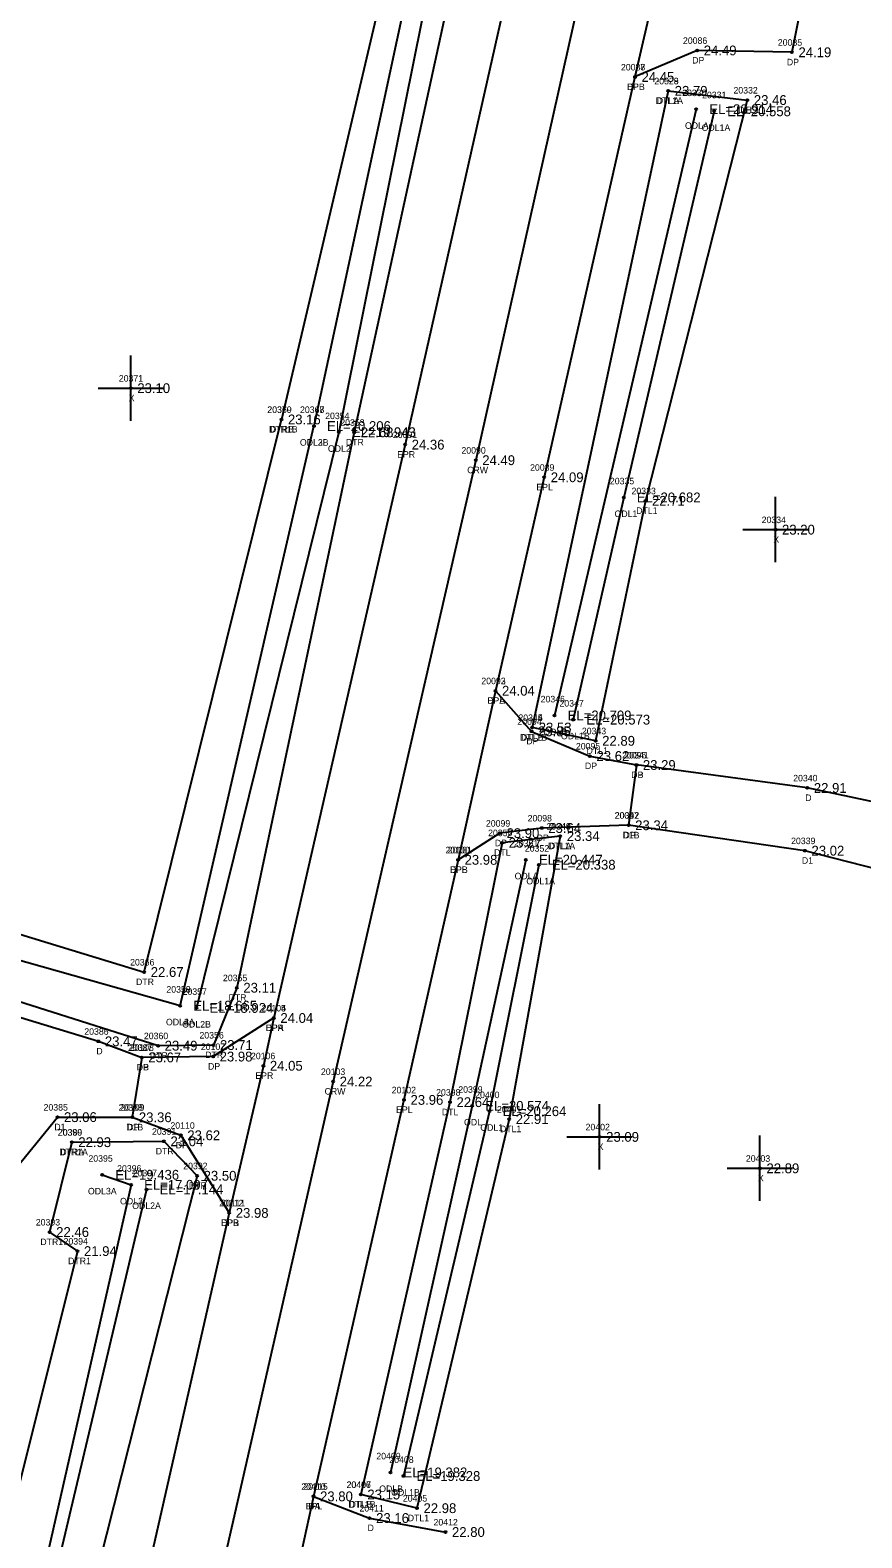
# Model space of a CAD drawing. Extents: x 2655177 to 2656219, y 761780 to 764748.
# Drawn here: x 2655809.5 to 2655936.8, y 763790 to 764020.7 of the extents above; entities that cross this region are included whole.
import ezdxf

# ---------------------------------------------------------------- set-up
doc = ezdxf.new("R2010")
doc.units = 0
for name, color, linetype in [('RD_DTM_BkLn1', 7, 'Continuous'), ('RD_EX_Driveway', 7, 'Continuous'), ('RD_EX_Driveway_txCode', 7, 'Continuous'), ('RD_EX_H2O', 7, 'Continuous'), ('RD_EX_H2O_txCode', 7, 'Continuous'), ('RD_EX_Misc', 7, 'Continuous'), ('RD_EX_Misc_txCode', 7, 'Continuous'), ('RD_EX_Road', 7, 'Continuous'), ('RD_EX_Road_txCode', 7, 'Continuous'), ('RD_EX_TX_Driveway_ELEV', 7, 'Continuous'), ('RD_EX_TX_H2O_ELEV', 7, 'Continuous'), ('RD_EX_TX_Misc_ELEV', 7, 'Continuous'), ('RD_EX_TX_Road_ELEV', 7, 'Continuous'), ('RD_HC_Survey_ELEV', 7, 'Continuous'), ('RD_HC_Survey_txCode', 7, 'Continuous'), ('RD_SMD_Locator', 7, 'Continuous')]:
    doc.layers.add(name, color=color, linetype=linetype)

msp = doc.modelspace()

# ---------------------------------------------------------------- linework, layer by layer
at = {"layer": 'RD_DTM_BkLn1'}
msp.add_lwpolyline([(2656052.36, 764720.46), (2656029.22, 764619.66), (2656007.41, 764523.97), (2655985.61, 764427.64), (2655963.53, 764330.64), (2655941.2, 764233.56), (2655920.06, 764141.06), (2655898.52, 764047.86), (2655877.71, 763954.88), (2655855.89, 763859.81), (2655834.07, 763763.97), (2655811.81, 763666.79), (2655790.48, 763573.22), (2655769.27, 763483.63), (2655747.64, 763389.32), (2655725.4, 763293.96), (2655721.51, 763275.9)], dxfattribs=at)
at = {"layer": 'RD_EX_Driveway'}
for points in [[(2655908.15, 764039.87), (2655916.78, 764031.64), (2655928.16, 764027.89), (2655926.1, 764017.29), (2655911.6, 764017.57), (2655902.08, 764013.51)], [(2655880.73, 763919.6), (2655886.23, 763913.39), (2655895.19, 763909.61), (2655902.29, 763908.24), (2655901.11, 763899.02), (2655887.81, 763898.6), (2655881.42, 763897.81), (2655875, 763893.73)], [(2655968.03, 763896.35), (2655928.45, 763904.73), (2655902.29, 763908.24)], [(2655965.98, 763885.43), (2655928.09, 763895.13), (2655901.11, 763899.02)], [(2655759.7, 763884.33), (2655819.96, 763865.96), (2655826.61, 763863.5)], [(2655846.82, 763869.53), (2655837.52, 763863.63), (2655826.61, 763863.5), (2655825.16, 763854.34), (2655832.58, 763851.58), (2655839.99, 763839.71)], [(2655797.92, 763834.98), (2655813.7, 763854.36), (2655825.16, 763854.34)], [(2655852.89, 763796.34), (2655861.47, 763793.02), (2655873.08, 763790.88)]]:
    msp.add_lwpolyline(points, dxfattribs=at)
at = {"layer": 'RD_EX_H2O'}
for p, q in [((2655907.16, 764011.39), (2655886.35, 763913.97)), ((2655911.46, 764008.58), (2655889.78, 763915.82)), ((2655832.49, 763871.41), (2655852.96, 763960.1)), ((2655832.49, 763871.41), (2655760.74, 763891.62))]:
    msp.add_line(p, q, dxfattribs=at)
for points in [[(2655985.99, 764532.58), (2655990.84, 764527.53), (2655967.74, 764432.27), (2655946, 764335.4), (2655922.66, 764238.07), (2655902.06, 764145.42), (2655879.59, 764053.25), (2655859.1, 763959.14), (2655841.15, 763874.16), (2655837.57, 763865.39), (2655829.11, 763865.29), (2655761.29, 763886.78)], [(2655985.99, 764532.58), (2655980.45, 764530.42), (2655978.53, 764524.06), (2655957.73, 764434.81), (2655933.82, 764338.64), (2655911.79, 764241.24), (2655890.59, 764146.77), (2655869.91, 764054.39), (2655847.97, 763961.11)], [(2655986.13, 764527.03), (2655964.81, 764432.99), (2655941.76, 764337.09), (2655920.19, 764238.99), (2655899.24, 764145.84), (2655875.75, 764053.31), (2655856.78, 763959.16), (2655834.97, 763871.07)], [(2655983.66, 764527.79), (2655962.07, 764433.73), (2655939.64, 764337.32), (2655916.77, 764240.59), (2655893.69, 764145.91), (2655873.09, 764053.84), (2655852.96, 763960.1)], [(2655907.16, 764011.39), (2655919.27, 764009.98), (2655903.67, 763948.66), (2655896.06, 763911.94), (2655886.35, 763913.97)], [(2655914.18, 764008.26), (2655900.36, 763949.18), (2655892.64, 763915.18)], [(2655761.3, 763896.61), (2655826.98, 763876.56), (2655847.97, 763961.11)], [(2655890.65, 763897.36), (2655881.76, 763896.35), (2655873.77, 763856.65), (2655860.12, 763796.62)], [(2655890.65, 763897.36), (2655882.83, 763854.06), (2655868.72, 763794.53), (2655860.12, 763796.62)], [(2655885.39, 763893.75), (2655877.16, 763856.09), (2655864.66, 763800)], [(2655887.35, 763892.98), (2655879.82, 763855.27), (2655866.65, 763799.45)], [(2655815.89, 763850.53), (2655830, 763850.66), (2655835.07, 763845.39), (2655815.37, 763767.48), (2655802.69, 763714.59), (2655797.51, 763669.56), (2655775.58, 763577.47), (2655772.9, 763561.56), (2655766.24, 763554.89), (2655760.22, 763554.42), (2655752.64, 763557.5), (2655751.61, 763561.47)], [(2655815.89, 763850.53), (2655812.51, 763836.78), (2655816.76, 763833.86), (2655801.46, 763772.79), (2655777.62, 763675.45), (2655757.45, 763580.99)], [(2655820.56, 763845.54), (2655824.97, 763844.01), (2655808.26, 763770.16), (2655784.18, 763674.18), (2655763.92, 763579.41), (2655759.35, 763565.01)], [(2655827.33, 763843.31), (2655809.9, 763769.59), (2655786.05, 763673.96), (2655766.11, 763579.1), (2655763.77, 763564.68)]]:
    msp.add_lwpolyline(points, dxfattribs=at)
at = {"layer": 'RD_EX_Misc'}
for p, q in [((2655824.92, 763960.9), (2655824.92, 763970.9)), ((2655819.92, 763965.9), (2655829.92, 763965.9)), ((2655923.58, 763939.25), (2655923.58, 763949.25)), ((2655918.58, 763944.25), (2655928.58, 763944.25)), ((2655896.67, 763846.34), (2655896.67, 763856.34)), ((2655891.67, 763851.34), (2655901.67, 763851.34)), ((2655921.2, 763841.53), (2655921.2, 763851.53)), ((2655916.2, 763846.53), (2655926.2, 763846.53))]:
    msp.add_line(p, q, dxfattribs=at)
at = {"layer": 'RD_EX_Road'}
for points in [[(2656041.72, 764723.31), (2656018.5, 764622.03), (2656002.75, 764552.49), (2655997.43, 764530.02), (2655974.74, 764429.64), (2655952.97, 764333.57), (2655930.52, 764235.7), (2655909.18, 764142.93), (2655887.93, 764050.57), (2655866.91, 763957.26), (2655846.82, 763869.53), (2655845.21, 763862.22), (2655839.99, 763839.71), (2655823.38, 763766.66), (2655801.33, 763669.93), (2655780.03, 763576.53), (2655774.26, 763551.85), (2655771.37, 763539.86), (2655759.09, 763486.9), (2655736.94, 763391.72), (2655715.19, 763296.77), (2655711.35, 763278.45)], [(2655930.84, 764138.62), (2655926.81, 764121.01), (2655909.26, 764045.26), (2655908.15, 764039.87), (2655902.08, 764013.51), (2655888.19, 763952.26), (2655880.73, 763919.6), (2655875, 763893.73), (2655866.73, 763857), (2655852.89, 763796.34), (2655850.73, 763786.52), (2655844.88, 763760.97), (2655822.62, 763664.7), (2655801.12, 763571.82), (2655780.32, 763481.64), (2655758.16, 763386.38), (2655736.73, 763291.27), (2655733.33, 763273.46)]]:
    msp.add_lwpolyline(points, dxfattribs=at)
at = {"layer": 'RD_SMD_Locator'}
for centre in [(2655911.6, 764017.57), (2655926.1, 764017.29), (2655902.08, 764013.51), (2655902.08, 764013.51), (2655907.16, 764011.39), (2655907.16, 764011.39), (2655919.27, 764009.98), (2655911.46, 764008.58), (2655914.18, 764008.26), (2655824.92, 763965.9), (2655847.97, 763961.11), (2655847.97, 763961.11), (2655852.96, 763960.1), (2655852.96, 763960.1), (2655856.78, 763959.16), (2655859.1, 763959.14), (2655866.91, 763957.26), (2655877.71, 763954.88), (2655888.19, 763952.26), (2655900.36, 763949.18), (2655903.67, 763948.66), (2655923.58, 763944.25), (2655880.73, 763919.6), (2655880.73, 763919.6), (2655889.78, 763915.82), (2655892.64, 763915.18), (2655886.23, 763913.39), (2655886.35, 763913.97), (2655886.35, 763913.97), (2655896.06, 763911.94), (2655895.19, 763909.61), (2655902.29, 763908.24), (2655902.29, 763908.24), (2655928.45, 763904.73), (2655901.11, 763899.02), (2655901.11, 763899.02), (2655881.42, 763897.81), (2655887.81, 763898.6), (2655890.65, 763897.36), (2655890.65, 763897.36), (2655881.76, 763896.35), (2655928.09, 763895.13), (2655875, 763893.73), (2655875, 763893.73), (2655885.39, 763893.75), (2655887.35, 763892.98), (2655826.98, 763876.56), (2655841.15, 763874.16), (2655832.49, 763871.41), (2655832.49, 763871.41), (2655834.97, 763871.07), (2655846.82, 763869.53), (2655846.82, 763869.53), (2655819.96, 763865.96), (2655829.11, 763865.29), (2655837.57, 763865.39), (2655826.61, 763863.5), (2655826.61, 763863.5), (2655837.52, 763863.63), (2655845.21, 763862.22), (2655855.89, 763859.81), (2655866.73, 763857), (2655873.77, 763856.65), (2655877.16, 763856.09), (2655879.82, 763855.27), (2655813.7, 763854.36), (2655825.16, 763854.34), (2655825.16, 763854.34), (2655882.83, 763854.06), (2655815.89, 763850.53), (2655815.89, 763850.53), (2655830, 763850.66), (2655832.58, 763851.58), (2655896.67, 763851.34), (2655921.2, 763846.53), (2655820.56, 763845.54), (2655824.97, 763844.01), (2655835.07, 763845.39), (2655827.33, 763843.31), (2655839.99, 763839.71), (2655839.99, 763839.71), (2655812.51, 763836.78), (2655816.76, 763833.86), (2655864.66, 763800), (2655866.65, 763799.45), (2655852.89, 763796.34), (2655852.89, 763796.34), (2655860.12, 763796.62), (2655860.12, 763796.62), (2655861.47, 763793.02), (2655868.72, 763794.53), (2655873.08, 763790.88)]:
    msp.add_circle(centre, 0.15, dxfattribs=at)

# ---------------------------------------------------------------- texts
at = {"layer": 'RD_EX_Driveway_txCode'}
for s, p in [('20086', (2655909.42, 764018.57)), ('20085', (2655923.94, 764018.29)), ('20087', (2655899.93, 764014.51)), ('DP', (2655910.83, 764015.57)), ('DP', (2655925.32, 764015.29)), ('DPB', (2655900.83, 764011.51)), ('20093', (2655878.57, 763920.6)), ('DPA', (2655879.46, 763917.6)), ('20094', (2655884.08, 763914.39)), ('DP', (2655885.45, 763911.39)), ('20095', (2655893.04, 763910.61)), ('DP', (2655894.42, 763907.61)), ('20096', (2655900.11, 763909.24)), ('20341', (2655900.45, 763909.24)), ('DP', (2655901.51, 763906.24)), ('DB', (2655901.51, 763906.24)), ('20340', (2655926.29, 763905.73)), ('D', (2655928.14, 763902.73)), ('20099', (2655879.27, 763898.81)), ('20098', (2655885.65, 763899.6)), ('20097', (2655898.96, 763900.02)), ('20342', (2655899, 763900.02)), ('DP', (2655880.64, 763895.81)), ('DP', (2655887.03, 763896.6)), ('D1B', (2655900.17, 763897.02)), ('DP', (2655900.33, 763897.02)), ('20339', (2655925.97, 763896.13)), ('20100', (2655873.08, 763894.73)), ('DPB', (2655873.74, 763891.73)), ('D1', (2655927.62, 763893.13)), ('20105', (2655844.95, 763870.53)), ('20386', (2655817.81, 763866.96)), ('DPA', (2655845.56, 763867.53)), ('D', (2655819.65, 763863.96)), ('20387', (2655824.5, 763864.5)), ('20108', (2655824.74, 763864.5)), ('20107', (2655835.64, 763864.63)), ('DP', (2655825.83, 763861.5)), ('DB', (2655825.83, 763861.5)), ('DP', (2655836.74, 763861.63)), ('20385', (2655811.58, 763855.36)), ('20388', (2655823.05, 763855.34)), ('20109', (2655823.29, 763855.34)), ('D1', (2655813.22, 763852.36)), ('D1B', (2655824.22, 763852.34)), ('DP', (2655824.38, 763852.34)), ('20110', (2655830.99, 763852.58)), ('DP', (2655831.8, 763849.58)), ('20111', (2655838.72, 763840.71)), ('DPB', (2655838.74, 763837.71)), ('20410', (2655851.02, 763797.34)), ('DA', (2655852.1, 763794.34)), ('20411', (2655859.92, 763794.02)), ('D', (2655861.16, 763791.02)), ('20412', (2655871.25, 763791.88))]:
    msp.add_text(s, height=1, dxfattribs=at).set_placement(p)
at = {"layer": 'RD_EX_H2O_txCode'}
for s, p in [('20328', (2655905.04, 764012.39)), ('20329', (2655905.04, 764012.39)), ('DTL1A', (2655905.26, 764009.39)), ('DTLA', (2655905.43, 764009.39)), ('20330', (2655909.3, 764010.58)), ('20331', (2655912.35, 764010.26)), ('20332', (2655917.15, 764010.98)), ('DTL1', (2655917.86, 764007.98)), ('ODLA', (2655909.73, 764005.58)), ('ODL1A', (2655912.28, 764005.26)), ('20370', (2655845.81, 763962.11)), ('20369', (2655845.83, 763962.11)), ('20367', (2655850.82, 763962.1)), ('20368', (2655850.82, 763962.1)), ('20354', (2655854.67, 763961.16)), ('DTR1B', (2655846.07, 763959.11)), ('DTRB', (2655846.23, 763959.11)), ('20353', (2655856.98, 763960.14)), ('ODL2B', (2655850.8, 763957.1)), ('ODL3B', (2655850.8, 763957.1)), ('ODL2', (2655855.09, 763956.16)), ('DTR', (2655857.83, 763957.14)), ('20335', (2655898.24, 763951.18)), ('20333', (2655901.55, 763949.66)), ('DTL1', (2655902.26, 763946.66)), ('ODL1', (2655898.95, 763946.18)), ('20346', (2655887.64, 763917.82)), ('20347', (2655890.52, 763917.18)), ('20344', (2655884.24, 763914.97)), ('20345', (2655884.24, 763914.97)), ('DTL1B', (2655884.47, 763911.97)), ('DTLB', (2655884.64, 763911.97)), ('ODLB', (2655888.06, 763912.82)), ('ODL1B', (2655890.76, 763912.18)), ('20343', (2655893.95, 763912.94)), ('DTL1', (2655894.66, 763909.94)), ('20348', (2655888.54, 763898.36)), ('20349', (2655888.54, 763898.36)), ('20350', (2655879.6, 763897.35)), ('DTL', (2655880.52, 763894.35)), ('20351', (2655883.56, 763895.75)), ('20352', (2655885.23, 763894.98)), ('DTL1A', (2655888.76, 763895.36)), ('DTLA', (2655888.92, 763895.36)), ('ODLA', (2655883.66, 763890.75)), ('ODL1A', (2655885.45, 763889.98)), ('20366', (2655824.82, 763877.56)), ('20355', (2655839.03, 763875.16)), ('DTR', (2655825.72, 763874.56)), ('20358', (2655830.37, 763873.41)), ('20359', (2655830.37, 763873.41)), ('20357', (2655832.85, 763873.07)), ('DTR', (2655839.88, 763872.16)), ('ODL2A', (2655830.31, 763868.41)), ('ODL4A', (2655830.31, 763868.41)), ('20360', (2655826.93, 763866.29)), ('ODL2B', (2655832.8, 763868.07)), ('20356', (2655835.43, 763866.39)), ('DTR', (2655827.84, 763863.29)), ('DTR', (2655836.31, 763863.39)), ('20398', (2655871.65, 763857.65)), ('20399', (2655875.04, 763858.09)), ('20400', (2655877.63, 763857.27)), ('DTL', (2655872.52, 763854.65)), ('20401', (2655880.96, 763855.06)), ('ODL', (2655875.92, 763853.09)), ('ODL1', (2655878.41, 763852.27)), ('DTL1', (2655881.42, 763852.06)), ('20390', (2655813.74, 763851.53)), ('20389', (2655813.78, 763851.53)), ('20391', (2655828.17, 763851.66)), ('DTR1A', (2655813.97, 763848.53)), ('DTRA', (2655814.14, 763848.53)), ('20395', (2655818.44, 763847.54)), ('DTR', (2655828.74, 763848.66)), ('20396', (2655822.83, 763846.01)), ('20397', (2655825.21, 763845.31)), ('20392', (2655832.95, 763846.39)), ('DTR', (2655833.81, 763843.39)), ('ODL3A', (2655818.37, 763842.54)), ('ODL3', (2655823.28, 763841.01)), ('ODL2A', (2655825.14, 763840.31)), ('20393', (2655810.39, 763837.78)), ('DTR1', (2655811.08, 763834.78)), ('20394', (2655814.64, 763834.86)), ('DTR1', (2655815.33, 763831.86)), ('20409', (2655862.5, 763802)), ('20408', (2655864.49, 763801.45)), ('20406', (2655857.93, 763797.62)), ('20407', (2655857.96, 763797.62)), ('ODLB', (2655862.94, 763797)), ('DTL1B', (2655858.23, 763794.62)), ('DTLB', (2655858.4, 763794.62)), ('ODL1B', (2655864.77, 763796.45)), ('20405', (2655866.56, 763795.53)), ('DTL1', (2655867.31, 763792.53))]:
    msp.add_text(s, height=1, dxfattribs=at).set_placement(p)
at = {"layer": 'RD_EX_Misc_txCode'}
for s, p in [('20371', (2655823.09, 763966.9)), ('X', (2655824.61, 763963.9)), ('20334', (2655921.46, 763945.25)), ('X', (2655923.26, 763942.25)), ('20402', (2655894.52, 763852.34)), ('X', (2655896.36, 763849.34)), ('20403', (2655919.05, 763847.53)), ('X', (2655920.89, 763844.53))]:
    msp.add_text(s, height=1, dxfattribs=at).set_placement(p)
at = {"layer": 'RD_EX_Road_txCode'}
for s, p in [('20088', (2655899.93, 764014.51)), ('EPL', (2655900.88, 764011.51)), ('20091', (2655865.03, 763958.26)), ('EPR', (2655865.68, 763955.26)), ('20089', (2655886.03, 763953.26)), ('EPL', (2655886.98, 763950.26)), ('20092', (2655878.57, 763920.6)), ('EPL', (2655879.52, 763917.6)), ('20101', (2655873.41, 763894.73)), ('EPL', (2655873.79, 763891.73)), ('20104', (2655844.95, 763870.53)), ('EPR', (2655845.59, 763867.53)), ('20106', (2655843.31, 763863.22)), ('EPR', (2655843.98, 763860.22)), ('20102', (2655864.85, 763858)), ('EPL', (2655865.52, 763855)), ('20112', (2655838.44, 763840.71)), ('EPR', (2655838.76, 763837.71)), ('20115', (2655851.34, 763797.34)), ('EPL', (2655851.69, 763794.34))]:
    msp.add_text(s, height=1, dxfattribs=at).set_placement(p)
at = {"layer": 'RD_EX_TX_Driveway_ELEV'}
for s, p in [('24.49', (2655912.6, 764016.82)), ('24.19', (2655927.1, 764016.54)), ('24.45', (2655903.08, 764012.76)), ('24.04', (2655881.73, 763918.85)), ('23.85', (2655887.23, 763912.64)), ('23.62', (2655896.19, 763908.86)), ('23.29', (2655903.29, 763907.49)), ('23.29', (2655903.29, 763907.49)), ('22.91', (2655929.45, 763903.98)), ('23.64', (2655888.81, 763897.85)), ('23.34', (2655902.11, 763898.27)), ('23.34', (2655902.11, 763898.27)), ('23.90', (2655882.42, 763897.06)), ('23.98', (2655876, 763892.98)), ('23.02', (2655929.09, 763894.38)), ('24.04', (2655847.82, 763868.78)), ('23.47', (2655820.96, 763865.21)), ('23.67', (2655827.61, 763862.75)), ('23.67', (2655827.61, 763862.75)), ('23.98', (2655838.52, 763862.88)), ('23.06', (2655814.7, 763853.61)), ('23.36', (2655826.16, 763853.59)), ('23.36', (2655826.16, 763853.59)), ('23.62', (2655833.58, 763850.83)), ('23.98', (2655840.99, 763838.96)), ('23.80', (2655853.89, 763795.59)), ('23.16', (2655862.47, 763792.27)), ('22.80', (2655874.08, 763790.13))]:
    msp.add_text(s, height=1.5, dxfattribs=at).set_placement(p)
at = {"layer": 'RD_EX_TX_H2O_ELEV'}
for s, p in [('23.79', (2655908.16, 764010.64)), ('23.79', (2655908.16, 764010.64)), ('23.46', (2655920.27, 764009.23)), ('EL=20.914', (2655913.46, 764007.83)), ('EL=20.558', (2655916.18, 764007.51)), ('23.16', (2655848.97, 763960.36)), ('23.16', (2655848.97, 763960.36)), ('EL=20.206', (2655854.96, 763959.35)), ('EL=20.206', (2655854.96, 763959.35)), ('EL=19.943', (2655858.78, 763958.41)), ('22.68', (2655860.1, 763958.39)), ('EL=20.682', (2655902.36, 763948.43)), ('22.71', (2655904.67, 763947.91)), ('EL=20.709', (2655891.78, 763915.07)), ('EL=20.573', (2655894.64, 763914.43)), ('23.53', (2655887.35, 763913.22)), ('23.53', (2655887.35, 763913.22)), ('22.89', (2655897.06, 763911.19)), ('23.27', (2655882.76, 763895.6)), ('23.34', (2655891.65, 763896.61)), ('23.34', (2655891.65, 763896.61)), ('EL=20.447', (2655887.39, 763893)), ('EL=20.338', (2655889.35, 763892.23)), ('22.67', (2655827.98, 763875.81)), ('23.11', (2655842.15, 763873.41)), ('EL=18.665', (2655834.49, 763870.66)), ('EL=18.665', (2655834.49, 763870.66)), ('EL=18.924', (2655836.97, 763870.32)), ('23.49', (2655830.11, 763864.54)), ('23.71', (2655838.57, 763864.64)), ('22.64', (2655874.77, 763855.9)), ('EL=20.574', (2655879.16, 763855.34)), ('EL=20.264', (2655881.82, 763854.52)), ('22.91', (2655883.83, 763853.31)), ('22.93', (2655816.89, 763849.78)), ('22.93', (2655816.89, 763849.78)), ('23.04', (2655831, 763849.91)), ('EL=19.436', (2655822.56, 763844.79)), ('23.50', (2655836.07, 763844.64)), ('EL=17.097', (2655826.97, 763843.26)), ('EL=17.144', (2655829.33, 763842.56)), ('22.46', (2655813.51, 763836.03)), ('21.94', (2655817.76, 763833.11)), ('EL=19.382', (2655866.66, 763799.25)), ('EL=19.328', (2655868.65, 763798.7)), ('23.15', (2655861.12, 763795.87)), ('23.15', (2655861.12, 763795.87)), ('22.98', (2655869.72, 763793.78))]:
    msp.add_text(s, height=1.5, dxfattribs=at).set_placement(p)
at = {"layer": 'RD_EX_TX_Misc_ELEV'}
for s, p in [('23.10', (2655825.92, 763965.15)), ('23.20', (2655924.58, 763943.5)), ('23.09', (2655897.67, 763850.59)), ('22.89', (2655922.2, 763845.78))]:
    msp.add_text(s, height=1.5, dxfattribs=at).set_placement(p)
at = {"layer": 'RD_EX_TX_Road_ELEV'}
for s, p in [('24.45', (2655903.08, 764012.76)), ('24.36', (2655867.91, 763956.51)), ('24.09', (2655889.19, 763951.51)), ('24.04', (2655881.73, 763918.85)), ('23.98', (2655876, 763892.98)), ('24.04', (2655847.82, 763868.78)), ('24.05', (2655846.21, 763861.47)), ('23.96', (2655867.73, 763856.25)), ('23.98', (2655840.99, 763838.96)), ('23.80', (2655853.89, 763795.59))]:
    msp.add_text(s, height=1.5, dxfattribs=at).set_placement(p)
at = {"layer": 'RD_HC_Survey_ELEV'}
for s, p in [('24.49', (2655878.71, 763954.13)), ('24.22', (2655856.89, 763859.06))]:
    msp.add_text(s, height=1.5, dxfattribs=at).set_placement(p)
at = {"layer": 'RD_HC_Survey_txCode'}
for s, p in [('20090', (2655875.52, 763955.88)), ('CRW', (2655876.4, 763952.88)), ('20103', (2655854.02, 763860.81)), ('CRW', (2655854.58, 763857.81))]:
    msp.add_text(s, height=1, dxfattribs=at).set_placement(p)

doc.saveas('drawing.dxf')
